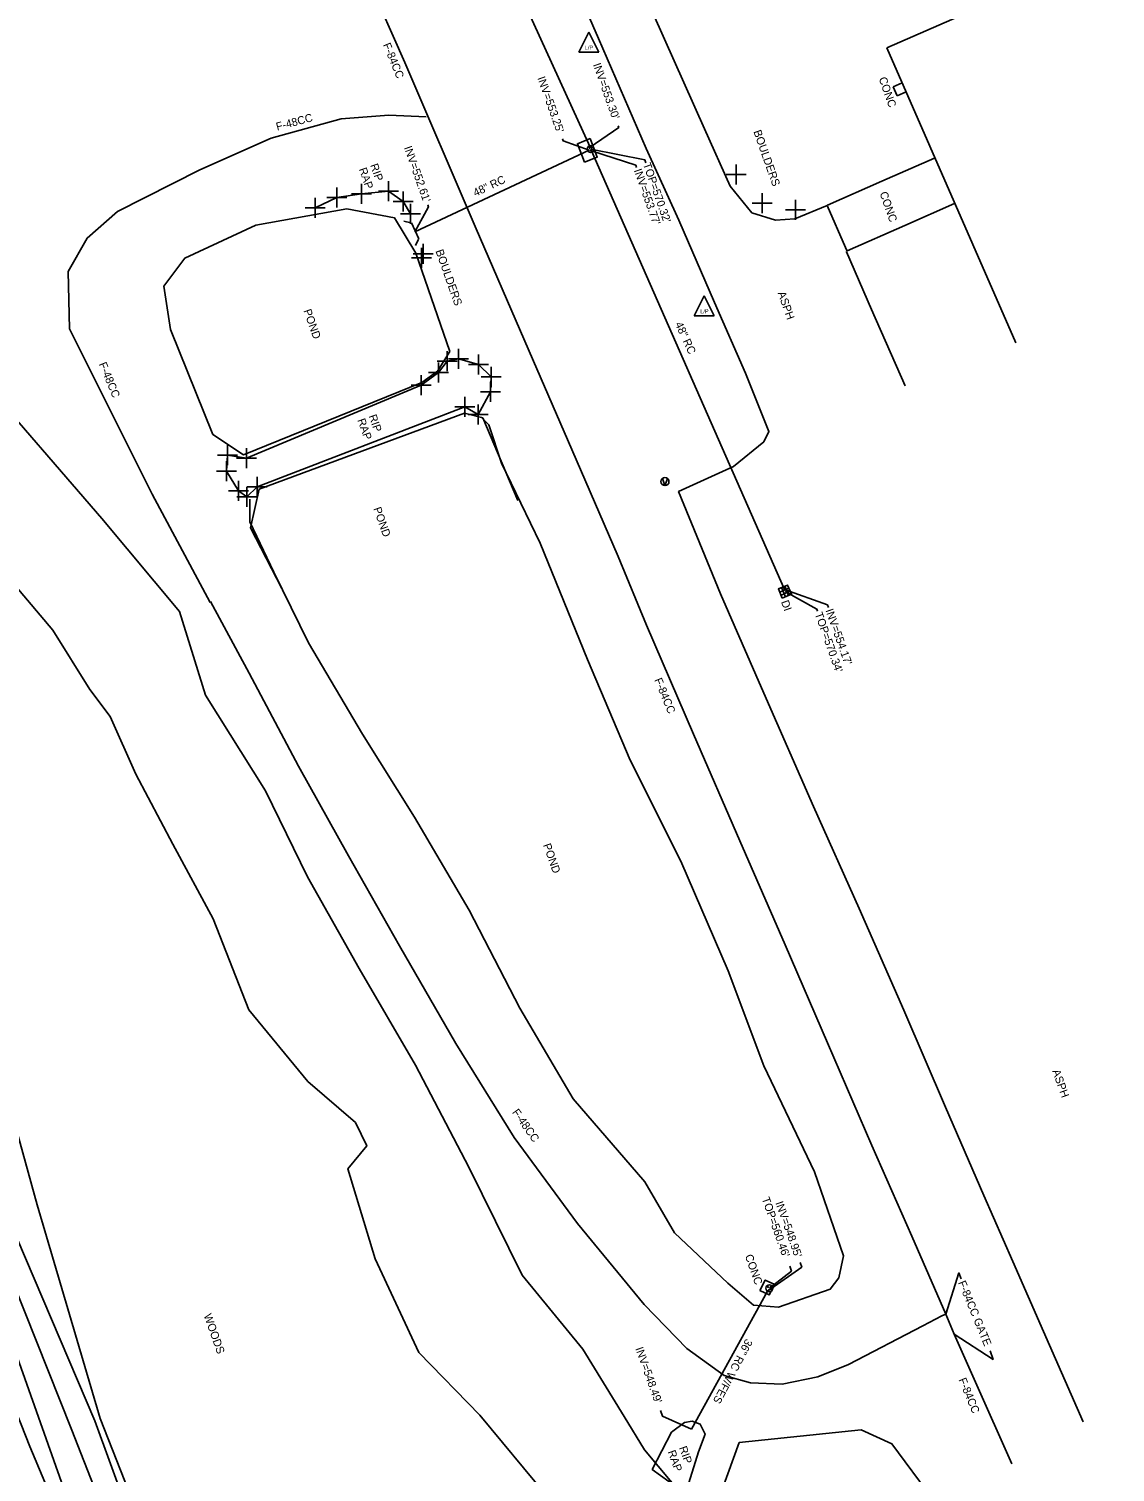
# Model space of a CAD drawing. Extents: x 2004847 to 2009016, y 1134161 to 1140101.
# Drawn here: x 2006408 to 2006951, y 1136162 to 1136883 of the extents above; entities that cross this region are included whole.
import ezdxf

# ---------------------------------------------------------------- set-up
doc = ezdxf.new("R2010")
doc.units = 0
for name, color, linetype in [('RD_EX_Bldg', 7, 'Continuous'), ('RD_EX_BldgApp', 7, 'Continuous'), ('RD_EX_Bridge', 7, 'Continuous'), ('RD_EX_Conc', 7, 'Continuous'), ('RD_EX_DR_Inlet', 7, 'Continuous'), ('RD_EX_DR_Inlet_txCode', 7, 'Continuous'), ('RD_EX_DR_Pipe', 7, 'Continuous'), ('RD_EX_DR_Pipe_txCode', 7, 'Continuous'), ('RD_EX_Driveway', 7, 'Continuous'), ('RD_EX_DV_Prop_txCode', 7, 'Continuous'), ('RD_EX_Fence_ChLk', 7, 'Continuous'), ('RD_EX_Fence_Other', 7, 'Continuous'), ('RD_EX_H2O', 7, 'Continuous'), ('RD_EX_Misc', 7, 'Continuous'), ('RD_EX_Road', 7, 'Continuous'), ('RD_EX_UT', 7, 'Continuous'), ('RD_EX_VEG', 7, 'Continuous'), ('RD_Sketch1', 7, 'Continuous'), ('RD_Sketch3', 7, 'Continuous')]:
    doc.layers.add(name, color=color, linetype=linetype)

msp = doc.modelspace()

# ---------------------------------------------------------------- linework, layer by layer
at = {"layer": 'RD_EX_Bldg'}
for q in [(2007268.88, 1137062.52), (2006901.33, 1136726.25)]:
    msp.add_line((2006836.89, 1136873.58), q, dxfattribs=at)
at = {"layer": 'RD_EX_BldgApp'}
msp.add_lwpolyline([(2006817.09, 1136772.18), (2006845.87, 1136784.84), (2006870.76, 1136795.75)], dxfattribs=at)
at = {"layer": 'RD_EX_Bridge'}
for p, q in [((2006598.84, 1136786.19), (2006595.38, 1136787)), ((2006602.83, 1136778.14), (2006599.15, 1136786.15)), ((2006602.75, 1136778.02), (2006601.18, 1136774.82))]:
    msp.add_line(p, q, dxfattribs=at)
at = {"layer": 'RD_EX_Conc'}
for p, q in [((2006844.54, 1136856.08), (2006840.07, 1136854.18)), ((2006841.99, 1136849.67), (2006840.07, 1136854.18)), ((2006846.51, 1136851.59), (2006841.99, 1136849.67))]:
    msp.add_line(p, q, dxfattribs=at)
for points in [[(2006688.53, 1136828.24), (2006682.14, 1136825.71), (2006685.7, 1136816.48)], [(2006685.7, 1136816.48), (2006692.09, 1136819), (2006688.53, 1136828.24)], [(2006860.74, 1136818.48), (2006834.32, 1136806.93), (2006807.19, 1136794.95)], [(2006780.86, 1136255.43), (2006776.09, 1136257.65), (2006773.31, 1136252.52)], [(2006773.31, 1136252.52), (2006778.08, 1136250.31), (2006780.86, 1136255.43)]]:
    msp.add_lwpolyline(points, dxfattribs=at)
at = {"layer": 'RD_EX_DR_Inlet'}
for p, q in [((2006783.35, 1136601.61), (2006787.95, 1136603.56)), ((2006784.01, 1136600.04), (2006788.61, 1136601.99)), ((2006784.25, 1136603.84), (2006786.2, 1136599.23)), ((2006785.81, 1136604.5), (2006787.76, 1136599.89))]:
    msp.add_line(p, q, dxfattribs=at)
msp.add_lwpolyline([(2006784.63, 1136598.57), (2006782.68, 1136603.18), (2006787.29, 1136605.12), (2006789.24, 1136600.52)], close=True, dxfattribs=at)
for centre, radius in [((2006688.83, 1136823.02), 1.75), ((2006688.17, 1136823.65), 0.175), ((2006688.75, 1136822.36), 0.175), ((2006689.39, 1136823.58), 0.175), ((2006778.15, 1136253.58), 1.75), ((2006777.48, 1136254.21), 0.175), ((2006778.06, 1136252.92), 0.175), ((2006778.71, 1136254.14), 0.175)]:
    msp.add_circle(centre, radius, dxfattribs=at)
at = {"layer": 'RD_EX_DR_Inlet_txCode'}
for points in [[(2006688.52, 1136824.01), (2006702.8, 1136833.82), (2006702.5, 1136834.66)], [(2006687.96, 1136822.53), (2006675, 1136827.08), (2006674.62, 1136828.17)], [(2006688.83, 1136823.02), (2006715.92, 1136817.61), (2006716.45, 1136816.1)], [(2006689.19, 1136822.13), (2006711.35, 1136814.98), (2006711.77, 1136813.81)], [(2006600.81, 1136781.73), (2006607.62, 1136794.19), (2006607.28, 1136795.17)], [(2006785.7, 1136602.94), (2006807.21, 1136595.21), (2006807.68, 1136593.87)], [(2006786.02, 1136601.81), (2006801.81, 1136593.11), (2006802.19, 1136592.04)]]:
    msp.add_lwpolyline(points, dxfattribs=at)
at = {"layer": 'RD_EX_DR_Pipe'}
for p, q in [((2006688.52, 1136824.01), (2006595.55, 1137027.33)), ((2006687.96, 1136822.53), (2006600.81, 1136781.73)), ((2006785.7, 1136602.94), (2006689.19, 1136822.13)), ((2006777.24, 1136252.1), (2006739.13, 1136183.09))]:
    msp.add_line(p, q, dxfattribs=at)
at = {"layer": 'RD_EX_Driveway'}
for points in [[(2006320.55, 1136558.36), (2006344.22, 1136462.95), (2006367.47, 1136387.76), (2006397.5, 1136288.99), (2006440.84, 1136187.25), (2006478.74, 1136083.47), (2006518.32, 1135988.65), (2006563.43, 1135904.15)], [(2006551.41, 1135897.85), (2006505.13, 1135983.38), (2006469.38, 1136080.46), (2006429.34, 1136182.74), (2006387.99, 1136286.09), (2006354.86, 1136380.53), (2006334.03, 1136460.8), (2006306.37, 1136551.19)]]:
    msp.add_lwpolyline(points, dxfattribs=at)
at = {"layer": 'RD_EX_DV_Prop_txCode'}
for p, q in [((2006761.51, 1136805.32), (2006761.51, 1136815.32)), ((2006756.51, 1136810.32), (2006766.51, 1136810.32)), ((2006561.89, 1136793.83), (2006561.89, 1136803.83)), ((2006569.24, 1136800.66), (2006579.24, 1136800.66)), ((2006574.24, 1136795.66), (2006574.24, 1136805.66)), ((2006582.68, 1136802.02), (2006592.68, 1136802.02)), ((2006587.68, 1136797.02), (2006587.68, 1136807.02)), ((2006594.98, 1136791.74), (2006594.98, 1136801.74)), ((2006774.54, 1136790.92), (2006774.54, 1136800.92)), ((2006545.96, 1136793.7), (2006555.96, 1136793.7)), ((2006550.96, 1136788.7), (2006550.96, 1136798.7)), ((2006556.89, 1136798.83), (2006566.89, 1136798.83)), ((2006589.98, 1136796.74), (2006599.98, 1136796.74)), ((2006598.73, 1136785.71), (2006598.73, 1136795.71)), ((2006769.54, 1136795.92), (2006779.54, 1136795.92)), ((2006791.28, 1136787.66), (2006791.28, 1136797.66)), ((2006593.73, 1136790.71), (2006603.73, 1136790.71)), ((2006786.28, 1136792.66), (2006796.28, 1136792.66)), ((2006604.21, 1136763.61), (2006604.21, 1136773.61)), ((2006605.03, 1136765.63), (2006605.03, 1136775.63)), ((2006599.21, 1136768.61), (2006609.21, 1136768.61)), ((2006600.03, 1136770.63), (2006610.03, 1136770.63)), ((2006616.99, 1136712), (2006616.99, 1136722)), ((2006622.66, 1136713.21), (2006622.66, 1136723.21)), ((2006611.99, 1136717), (2006621.99, 1136717)), ((2006612.68, 1136706.36), (2006612.68, 1136716.36)), ((2006617.66, 1136718.21), (2006627.66, 1136718.21)), ((2006627.71, 1136715.35), (2006637.71, 1136715.35)), ((2006632.71, 1136710.35), (2006632.71, 1136720.35)), ((2006638.98, 1136704.22), (2006638.98, 1136714.22)), ((2006603.95, 1136700.03), (2006603.95, 1136710.03)), ((2006607.68, 1136711.36), (2006617.68, 1136711.36)), ((2006633.98, 1136709.22), (2006643.98, 1136709.22)), ((2006638.74, 1136696.75), (2006638.74, 1136706.75)), ((2006598.95, 1136705.03), (2006608.95, 1136705.03)), ((2006633.74, 1136701.75), (2006643.74, 1136701.75)), ((2006620.91, 1136694.24), (2006630.91, 1136694.24)), ((2006625.91, 1136689.24), (2006625.91, 1136699.24)), ((2006632.51, 1136685.39), (2006632.51, 1136695.39)), ((2006627.51, 1136690.39), (2006637.51, 1136690.39)), ((2006507.1, 1136665.04), (2006507.1, 1136675.04)), ((2006516.67, 1136663.57), (2006516.67, 1136673.57)), ((2006502.1, 1136670.04), (2006512.1, 1136670.04)), ((2006506.74, 1136657.06), (2006506.74, 1136667.06)), ((2006511.67, 1136668.57), (2006521.67, 1136668.57)), ((2006501.74, 1136662.06), (2006511.74, 1136662.06)), ((2006512.59, 1136647.23), (2006512.59, 1136657.23)), ((2006522.06, 1136649.13), (2006522.06, 1136659.13)), ((2006507.59, 1136652.23), (2006517.59, 1136652.23)), ((2006511.77, 1136649.25), (2006521.77, 1136649.25)), ((2006516.77, 1136644.25), (2006516.77, 1136654.25)), ((2006517.06, 1136654.13), (2006527.06, 1136654.13))]:
    msp.add_line(p, q, dxfattribs=at)
at = {"layer": 'RD_EX_Fence_ChLk'}
for points in [[(2006679.24, 1137088.33), (2006675.23, 1137079.68), (2006645.11, 1137014.05), (2006619.7, 1136957.79), (2006602.85, 1136920.73), (2006577.74, 1136907.45), (2006595.79, 1136866.35), (2006630.95, 1136784.35), (2006655.83, 1136727.02), (2006681.52, 1136667.81), (2006702.55, 1136619.37)], [(2006498.49, 1136596.3), (2006469.56, 1136650.57), (2006428.14, 1136733.2), (2006427.5, 1136761.75), (2006437.03, 1136778.51), (2006452.19, 1136791.78), (2006493.36, 1136812.67), (2006528.93, 1136828.47), (2006564.05, 1136838.21), (2006587.8, 1136839.94), (2006606.48, 1136839.16)], [(2006899.36, 1136165.83), (2006881.27, 1136206.68), (2006870.61, 1136230.63), (2006866.37, 1136240.67), (2006849.39, 1136279.56), (2006829.42, 1136325.04), (2006807.26, 1136376.28), (2006786, 1136425.29), (2006763.44, 1136477.21), (2006740.23, 1136530.52), (2006716.75, 1136585.06), (2006702.55, 1136619.37)], [(2006498.64, 1136596.86), (2006517.92, 1136561.03), (2006542.7, 1136514.52), (2006567.76, 1136469.82), (2006593.24, 1136424.74), (2006621.34, 1136375.86), (2006650.46, 1136328.97), (2006682.24, 1136286.01), (2006715.56, 1136245.41), (2006736.85, 1136223.48), (2006755.48, 1136210.05), (2006768.68, 1136206.28), (2006784.52, 1136205.7), (2006802.43, 1136209.37), (2006817.72, 1136215.56), (2006854.84, 1136234.89), (2006864.46, 1136239.76), (2006866.37, 1136240.67)]]:
    msp.add_lwpolyline(points, dxfattribs=at)
at = {"layer": 'RD_EX_Fence_Other'}
msp.add_lwpolyline([(2006288.09, 1136544.58), (2006318.68, 1136456.24), (2006344.96, 1136379.7), (2006379.57, 1136282.04), (2006416.49, 1136178.27), (2006490.52, 1135969.29)], dxfattribs=at)
at = {"layer": 'RD_EX_H2O'}
for points in [[(2006618.29, 1136721.81), (2006601.31, 1136771.06), (2006590.72, 1136788.6), (2006566.82, 1136793.09), (2006521.28, 1136784.93), (2006485.76, 1136768.52), (2006475.36, 1136754.51), (2006478.64, 1136732.76), (2006499.79, 1136680.41), (2006515.11, 1136670.13), (2006604.4, 1136706.28)], [(2006265.22, 1136726.31), (2006271.15, 1136727.64), (2006296.68, 1136716.04), (2006315.6, 1136692.72), (2006327.7, 1136677.63), (2006357.88, 1136662), (2006370.28, 1136653.37), (2006374.25, 1136642.86), (2006394.43, 1136612.6), (2006419.83, 1136582.48), (2006438.3, 1136552.85)], [(2006618.29, 1136721.81), (2006612.24, 1136711.96), (2006604.4, 1136706.28)], [(2006633.85, 1136689.24), (2006637.88, 1136685.11), (2006644.17, 1136666.03), (2006663.56, 1136626.05), (2006687.15, 1136567.95), (2006708.54, 1136517.6), (2006733.85, 1136467.11), (2006757.57, 1136412.34), (2006775.42, 1136364.83), (2006800.67, 1136311.81), (2006815.18, 1136269.83), (2006812.94, 1136258.75), (2006808.6, 1136253.18), (2006782.75, 1136244.17), (2006770.18, 1136245.07), (2006757.46, 1136256.18), (2006730.72, 1136281.26), (2006715.9, 1136306.85), (2006680.02, 1136348.36), (2006653.4, 1136393.56), (2006628, 1136442.57), (2006600.61, 1136489.06), (2006574.6, 1136530.62), (2006547.62, 1136576.28), (2006530.29, 1136611.46), (2006518.28, 1136636.68), (2006518.28, 1136648.04)], [(2006625.61, 1136691.02), (2006522.93, 1136653.07), (2006518.71, 1136633.73), (2006534.41, 1136603.35)], [(2006652.4, 1136647.41), (2006634.83, 1136688.68), (2006625.61, 1136691.02)], [(2006438.3, 1136552.85), (2006448.54, 1136539.41), (2006461.27, 1136510.56), (2006479.77, 1136475.59), (2006499.97, 1136438.29), (2006517.79, 1136392.8), (2006547.32, 1136356.98), (2006571.18, 1136336.4), (2006576.82, 1136324.85), (2006567.33, 1136313.35), (2006581.05, 1136268.26), (2006602.92, 1136221.41), (2006633.34, 1136190.16), (2006666.45, 1136150.11), (2006686.25, 1136119.02), (2006695.17, 1136104.33)]]:
    msp.add_lwpolyline(points, dxfattribs=at)
at = {"layer": 'RD_EX_Misc'}
for points in [[(2006598.73, 1136790.71), (2006594.98, 1136796.74), (2006587.68, 1136802.02), (2006574.24, 1136800.66), (2006561.89, 1136798.83), (2006550.96, 1136793.7)], [(2006632.51, 1136690.39), (2006638.74, 1136701.75), (2006638.98, 1136709.22), (2006632.71, 1136715.35), (2006622.66, 1136718.21), (2006616.99, 1136717), (2006612.68, 1136711.36), (2006603.95, 1136705.03), (2006516.67, 1136668.57), (2006507.1, 1136670.04), (2006506.74, 1136662.06), (2006512.59, 1136652.23), (2006516.77, 1136649.25), (2006522.06, 1136654.13)], [(2006632.51, 1136690.39), (2006625.91, 1136694.24), (2006522.06, 1136654.13)], [(2006736.22, 1136150.97), (2006719.55, 1136163.06), (2006729.23, 1136181.59), (2006735.77, 1136186.55), (2006739.57, 1136187.15), (2006743.58, 1136185.74), (2006746.03, 1136180.64), (2006742.78, 1136171.89), (2006736.22, 1136150.97)]]:
    msp.add_lwpolyline(points, dxfattribs=at)
at = {"layer": 'RD_EX_Road'}
for points in [[(2006775.35, 1136676.67), (2006777.94, 1136681.79), (2006766.22, 1136711.06), (2006750.72, 1136746.34), (2006732.8, 1136787.49), (2006716.56, 1136823.39), (2006692.62, 1136878.29), (2006667.71, 1136935.76), (2006658.83, 1136989.32), (2006664.28, 1137021.7), (2006686.47, 1137064.98), (2006711.13, 1137087.73), (2006777.9, 1137121.36), (2006828.33, 1137143.11), (2006876.2, 1137164.06), (2006930.82, 1137188.1), (2006975.41, 1137207.33), (2006977.78, 1137208.53)], [(2006988, 1137178.88), (2006944.02, 1137159.91), (2006889.23, 1137135.95), (2006843.16, 1137116.33), (2006788.51, 1137093.13), (2006729.84, 1137064.4), (2006709.52, 1137045.09), (2006694.58, 1137017.11), (2006689.48, 1136987.51), (2006695.48, 1136949.01), (2006720.18, 1136890.34), (2006745.77, 1136833.11), (2006758.62, 1136804.47), (2006769.4, 1136791.11), (2006781.15, 1136787.46), (2006790.88, 1136788.14), (2006807.13, 1136794.87), (2006816.23, 1136773.75), (2006817.04, 1136771.98), (2006816.65, 1136771.74), (2006829.3, 1136742.84), (2006846.1, 1136704.6)], [(2006775.35, 1136676.67), (2006760.27, 1136664.29), (2006732.79, 1136651.79), (2006753.78, 1136600.72), (2006775.36, 1136551.03), (2006800.3, 1136494.47), (2006823.03, 1136443.35), (2006845.39, 1136392.62), (2006866.17, 1136344.04), (2006885.34, 1136300.02), (2006899.96, 1136266.91), (2006915.16, 1136232.03), (2006935.01, 1136186.81)]]:
    msp.add_lwpolyline(points, dxfattribs=at)
at = {"layer": 'RD_EX_UT'}
for p, q in [((2006682.88, 1136871.44), (2006687.88, 1136881.44)), ((2006687.88, 1136881.44), (2006692.88, 1136871.44)), ((2006682.88, 1136871.44), (2006692.88, 1136871.44)), ((2006740.6, 1136739.6), (2006745.6, 1136749.6)), ((2006745.6, 1136749.6), (2006750.6, 1136739.6)), ((2006740.6, 1136739.6), (2006750.6, 1136739.6)), ((2006725.95, 1136654.81), (2006724.64, 1136658.29)), ((2006725.95, 1136654.81), (2006727.27, 1136658.25))]:
    msp.add_line(p, q, dxfattribs=at)
msp.add_circle((2006725.95, 1136656.8), 2, dxfattribs=at)
at = {"layer": 'RD_EX_VEG'}
for points in [[(2006483.22, 1136591.89), (2006444.32, 1136638.34), (2006381.57, 1136710.72), (2006332.03, 1136760.83)], [(2006859.96, 1136148.24), (2006839.42, 1136175.89), (2006823.99, 1136182.79), (2006763.07, 1136176.47), (2006751.64, 1136145.15), (2006735.34, 1136149.37), (2006715.68, 1136172.85), (2006705.52, 1136189.46), (2006684.89, 1136223.19), (2006654.56, 1136260.07), (2006627.78, 1136314.06), (2006601.18, 1136365.04), (2006573.02, 1136413.42), (2006547.1, 1136459.29), (2006526.17, 1136502.27), (2006496.1, 1136550.13), (2006483.22, 1136591.89)], [(2006322.66, 1136558.8), (2006353.02, 1136466.99), (2006384.47, 1136394.39), (2006412, 1136295.24), (2006443.56, 1136188.55), (2006484.2, 1136085.12), (2006524.25, 1135990.06), (2006569.76, 1135908.33), (2006606.1, 1135833.79)], [(2006565.48, 1135819.09), (2006528.32, 1135891.1), (2006489.01, 1135976.52), (2006450.61, 1136073.8), (2006408.25, 1136174.58), (2006367.76, 1136276.74), (2006335.67, 1136376.41), (2006311.68, 1136456.94), (2006280.68, 1136541.58)]]:
    msp.add_lwpolyline(points, dxfattribs=at)
at = {"layer": 'RD_Sketch1'}
for points in [[(2006777.24, 1136252.1), (2006794.35, 1136264.19), (2006793.54, 1136266.5)], [(2006778.15, 1136253.58), (2006789.21, 1136262.21), (2006788.34, 1136264.66)], [(2006739.13, 1136183.09), (2006724.63, 1136189.68), (2006723.66, 1136192.44)]]:
    msp.add_lwpolyline(points, dxfattribs=at)
at = {"layer": 'RD_Sketch3'}
for points in [[(2006874.02, 1136258.3), (2006872.96, 1136261.28), (2006866.37, 1136240.67)], [(2006888.51, 1136222.3), (2006890.01, 1136218.04), (2006870.61, 1136230.63)]]:
    msp.add_lwpolyline(points, dxfattribs=at)

# ---------------------------------------------------------------- texts
at = {"layer": 'RD_EX_DR_Inlet_txCode'}
for s, p in [("INV=553.30'", (2006689.88, 1136865.23)), ("INV=553.25'", (2006662.05, 1136858.54)), ("INV=552.61'", (2006595.37, 1136823.76)), ("TOP=570.32'", (2006714.85, 1136815.46)), ("INV=553.77'", (2006710.33, 1136812.39)), ('DI', (2006783.92, 1136596.72)), ("TOP=570.34'", (2006800.78, 1136590.72)), ("INV=554.17'", (2006806.14, 1136592.46))]:
    msp.add_text(s, height=4, rotation=289.44941, dxfattribs=at).set_placement(p)
at = {"layer": 'RD_EX_DR_Pipe_txCode'}
for rotation, p in [(25.25622, (2006631.14, 1136799.15)), (294.54077, (2006730.86, 1136735.59))]:
    msp.add_text('48" RC', height=4, rotation=rotation, dxfattribs=at).set_placement(p)
at = {"layer": 'RD_EX_UT'}
for p in [(2006685.87, 1136872.72), (2006743.59, 1136740.89)]:
    msp.add_text('L/P', height=2, dxfattribs=at).set_placement(p)
at = {"layer": 'RD_Sketch1'}
for s, rotation, p in [("TOP=560.46'", 289.44941, (2006774.28, 1136298.41)), ("INV=548.95'", 289.44941, (2006781.1, 1136296.3)), ("INV=548.49'", 289.44941, (2006711.08, 1136223.45)), ('36" RC W/FES', 242.06843, (2006766.44, 1136228.65))]:
    msp.add_text(s, height=4, rotation=rotation, dxfattribs=at).set_placement(p)
at = {"layer": 'RD_Sketch3'}
for s, rotation, p in [('F-84CC', 292.41314, (2006584.8, 1136875.17)), ('CONC', 289.44941, (2006832.78, 1136858.28)), ('F-48CC', 15.04435, (2006532.03, 1136832.19)), ('BOULDERS', 289.44941, (2006770.1, 1136831.79)), ('RIP', 289.44941, (2006578.46, 1136814.97)), ('RAP', 289.44941, (2006572.8, 1136812.98)), ('CONC', 289.44941, (2006833.21, 1136800.97)), ('BOULDERS', 289.44941, (2006611.13, 1136772.09)), ('ASPH', 289.44941, (2006782.26, 1136751.09)), ('POND', 289.44941, (2006545.1, 1136742.24)), ('F-48CC', 292.41314, (2006442.75, 1136715.58)), ('RAP', 289.44941, (2006572.07, 1136687.58)), ('RIP', 289.44941, (2006577.73, 1136689.58)), ('POND', 289.44941, (2006580.03, 1136643.3)), ('F-84CC', 292.41314, (2006720.52, 1136557.71)), ('POND', 289.44941, (2006664.93, 1136475.16)), ('ASPH', 289.44941, (2006919.59, 1136362.18)), ('F-48CC', 305.13108, (2006649.33, 1136341.53)), ('CONC', 289.44941, (2006765.86, 1136269.77)), ('F-84CC GATE', 292.41314, (2006872.45, 1136256.44)), ('WOODS', 289.44941, (2006495.22, 1136240.04)), ('F-84CC', 292.41314, (2006872.67, 1136207.89)), ('RIP', 289.44941, (2006732.93, 1136173.89)), ('RAP', 289.44941, (2006727.27, 1136171.89))]:
    msp.add_text(s, height=4, rotation=rotation, dxfattribs=at).set_placement(p)

doc.saveas('drawing.dxf')
